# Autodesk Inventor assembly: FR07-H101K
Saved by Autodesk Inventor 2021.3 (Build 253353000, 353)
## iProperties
Created: 2022-04
Part Number: FR07-H101K
Document SubType Name: Assembly
Designer: Administrator
Title: FR07-H101K v5
Author: Administrator
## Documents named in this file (2)
- c:\worker\convert-fusion-r02\tmp\job-1\13\output\files\15bac558-b20f-454c-9f6c-4870732dc52c\17692f33-3927-4927-9663-711b223a30fe.iam
- c:\worker\convert-fusion-r02\tmp\job-1\13\output\files\15bac558-b20f-454c-9f6c-4870732dc52c\Component1.ipt
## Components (1 placed, 1 different names)
1. Component1:1
